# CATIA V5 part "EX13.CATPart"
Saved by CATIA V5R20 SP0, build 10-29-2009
Part number: EX13
Bounding box of the stored display mesh (mm): x -57 to 57, y -57 to 57, z 0 to 15
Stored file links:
  E:\Nouveau dossier\tarek\mécaniquee\Catia\TP 0\EX13.CATPart
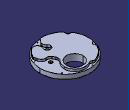
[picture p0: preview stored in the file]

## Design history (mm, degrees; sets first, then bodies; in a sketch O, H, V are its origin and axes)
Set1
  DatumSurface1 to DatumSurface61
Body1 (main body)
